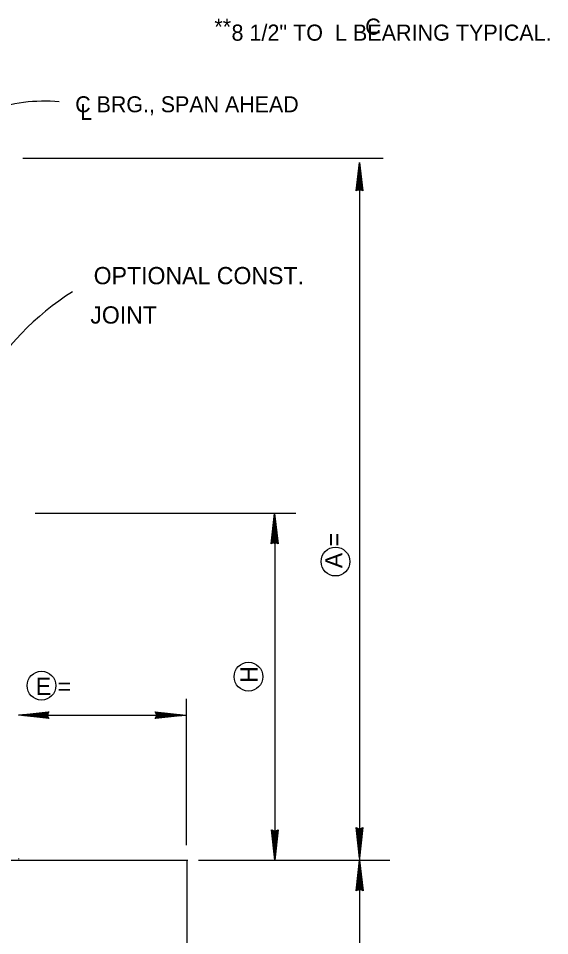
# Model space of a CAD drawing. Extents: x 1.6 to 6.29, y 2.8 to 7.08.
# Drawn here: x 4.232 to 4.616, y 5.231 to 5.896 of the extents above; entities that cross this region are included whole.
import ezdxf

# ---------------------------------------------------------------- set-up
doc = ezdxf.new("R2010")
doc.units = 0
doc.layers.add('Level 1', color=7, linetype='Continuous')
doc.layers.add('Level 5', color=7, linetype='Continuous')

msp = doc.modelspace()

# ---------------------------------------------------------------- linework, layer by layer
at = {"layer": 'Level 1'}
for p, q in [((4.23483, 5.79417), (4.49575, 5.79417)), ((4.47625, 5.77058), (4.47858, 5.79125)), ((4.47858, 5.79125), (4.47858, 5.13608)), ((4.47858, 5.77058), (4.47858, 5.79125)), ((4.47858, 5.79125), (4.48092, 5.77058)), ((4.47658, 5.77108), (4.47825, 5.78642)), ((4.47658, 5.77092), (4.47833, 5.78642)), ((4.47675, 5.77092), (4.47842, 5.78642)), ((4.47683, 5.77092), (4.4785, 5.78633)), ((4.477, 5.77092), (4.47875, 5.78633)), ((4.478, 5.77858), (4.4785, 5.78783)), ((4.47992, 5.77083), (4.47833, 5.78525)), ((4.4785, 5.78783), (4.479, 5.78583)), ((4.48017, 5.77092), (4.47858, 5.78533)), ((4.479, 5.78583), (4.47875, 5.78842)), ((4.47875, 5.78842), (4.47875, 5.772)), ((4.48033, 5.77092), (4.47875, 5.78542)), ((4.48058, 5.77108), (4.479, 5.78542)), ((4.4775, 5.7715), (4.478, 5.77858)), ((4.47833, 5.772), (4.47817, 5.78117)), ((4.47817, 5.78117), (4.4785, 5.78108)), ((4.47833, 5.77933), (4.47817, 5.772)), ((4.4785, 5.78108), (4.47833, 5.77933)), ((4.47908, 5.77175), (4.47842, 5.78233)), ((4.47842, 5.78233), (4.4795, 5.77158)), ((4.47858, 5.77167), (4.47625, 5.77058)), ((4.47842, 5.77208), (4.47692, 5.77108)), ((4.47692, 5.77108), (4.47725, 5.77158)), ((4.47783, 5.7725), (4.47717, 5.77217)), ((4.47717, 5.77217), (4.47867, 5.77183)), ((4.47725, 5.77158), (4.478, 5.77208)), ((4.47775, 5.77608), (4.4775, 5.7715)), ((4.47783, 5.77175), (4.47775, 5.77608)), ((4.478, 5.77792), (4.47783, 5.77175)), ((4.478, 5.77208), (4.47783, 5.7725)), ((4.47817, 5.772), (4.478, 5.77792)), ((4.4795, 5.77158), (4.47842, 5.77208)), ((4.48092, 5.77058), (4.47858, 5.77167)), ((4.47867, 5.77183), (4.4795, 5.7715)), ((4.47875, 5.772), (4.47908, 5.77683)), ((4.47908, 5.77683), (4.47908, 5.77175)), ((4.4795, 5.7715), (4.4805, 5.77108)), ((4.24383, 5.53717), (4.43258, 5.53717)), ((4.41475, 5.515), (4.41717, 5.53708)), ((4.41583, 5.51608), (4.41758, 5.5325)), ((4.41658, 5.52358), (4.41708, 5.53342)), ((4.41708, 5.53342), (4.41758, 5.53133)), ((4.41717, 5.515), (4.41717, 5.53708)), ((4.41717, 5.53708), (4.41967, 5.515)), ((4.41725, 5.53583), (4.41725, 5.28633)), ((4.41758, 5.53133), (4.41733, 5.53408)), ((4.41733, 5.53408), (4.41742, 5.5165)), ((4.41508, 5.51542), (4.41692, 5.53192)), ((4.41517, 5.51542), (4.417, 5.53192)), ((4.41533, 5.51542), (4.41708, 5.53183)), ((4.4155, 5.51542), (4.41733, 5.53183)), ((4.41692, 5.5165), (4.41675, 5.52633)), ((4.41675, 5.52633), (4.41708, 5.52625)), ((4.41858, 5.51533), (4.41692, 5.53067)), ((4.41708, 5.52625), (4.41692, 5.52442)), ((4.41775, 5.51625), (4.417, 5.5275)), ((4.417, 5.5275), (4.41817, 5.51608)), ((4.41883, 5.51542), (4.41717, 5.53075)), ((4.41908, 5.51542), (4.41742, 5.53083)), ((4.41933, 5.5155), (4.41758, 5.53083)), ((4.41608, 5.516), (4.41658, 5.52358)), ((4.41633, 5.52083), (4.41608, 5.516)), ((4.41642, 5.51625), (4.41633, 5.52083)), ((4.41658, 5.52283), (4.41642, 5.51625)), ((4.41675, 5.5165), (4.41658, 5.52283)), ((4.41692, 5.52442), (4.41675, 5.5165)), ((4.41742, 5.5165), (4.41775, 5.52167)), ((4.41775, 5.52167), (4.41775, 5.51625)), ((4.41717, 5.51617), (4.41475, 5.515)), ((4.417, 5.51658), (4.41542, 5.51558)), ((4.41542, 5.51558), (4.41575, 5.51608)), ((4.41642, 5.51708), (4.41567, 5.51675)), ((4.41567, 5.51675), (4.41725, 5.51642)), ((4.41575, 5.51608), (4.41658, 5.51658)), ((4.41658, 5.51658), (4.41642, 5.51708)), ((4.41817, 5.51608), (4.417, 5.51658)), ((4.41967, 5.515), (4.41717, 5.51617)), ((4.41725, 5.51642), (4.41817, 5.516)), ((4.41817, 5.516), (4.41925, 5.5155)), ((4.353, 5.40283), (4.353, 5.29683)), ((4.23158, 5.391), (4.25367, 5.3935)), ((4.25317, 5.39308), (4.23783, 5.39142)), ((4.25317, 5.39292), (4.23783, 5.39125)), ((4.25367, 5.3935), (4.2525, 5.391)), ((4.25267, 5.392), (4.25317, 5.39308)), ((4.33067, 5.39342), (4.35292, 5.391)), ((4.33183, 5.391), (4.33067, 5.39342)), ((4.33108, 5.39308), (4.34767, 5.39125)), ((4.33108, 5.393), (4.34767, 5.39117)), ((4.33108, 5.39292), (4.34767, 5.39108)), ((4.33117, 5.39317), (4.34767, 5.39133)), ((4.25367, 5.391), (4.23158, 5.391)), ((4.25367, 5.38858), (4.23158, 5.391)), ((4.23408, 5.391), (4.35033, 5.391)), ((4.23725, 5.39142), (4.23458, 5.39117)), ((4.23458, 5.39117), (4.25217, 5.39125)), ((4.23525, 5.39083), (4.23725, 5.39142)), ((4.24508, 5.39042), (4.23525, 5.39083)), ((4.25317, 5.38892), (4.23675, 5.39075)), ((4.25317, 5.389), (4.23675, 5.39075)), ((4.25317, 5.38883), (4.23675, 5.39067)), ((4.25325, 5.38933), (4.23683, 5.39108)), ((4.25317, 5.38908), (4.23683, 5.39092)), ((4.25325, 5.39267), (4.23792, 5.391)), ((4.25325, 5.39242), (4.23792, 5.39075)), ((4.24117, 5.39075), (4.2525, 5.392)), ((4.25242, 5.39158), (4.24117, 5.39075)), ((4.24233, 5.39058), (4.24233, 5.39083)), ((4.24233, 5.39083), (4.24425, 5.39075)), ((4.25217, 5.39075), (4.24233, 5.39058)), ((4.24425, 5.39075), (4.25217, 5.39058)), ((4.25258, 5.38983), (4.24508, 5.39042)), ((4.25217, 5.39058), (4.24583, 5.39042)), ((4.24583, 5.39042), (4.25242, 5.39025)), ((4.25217, 5.39125), (4.247, 5.39158)), ((4.247, 5.39158), (4.25242, 5.39158)), ((4.25242, 5.39025), (4.24775, 5.39008)), ((4.24775, 5.39008), (4.25258, 5.38983)), ((4.25208, 5.39042), (4.2515, 5.39017)), ((4.2515, 5.39017), (4.25192, 5.3895)), ((4.25192, 5.3895), (4.25225, 5.39108)), ((4.2525, 5.392), (4.25208, 5.39075)), ((4.25208, 5.39075), (4.253, 5.38925)), ((4.2525, 5.38958), (4.25208, 5.39042)), ((4.25225, 5.39108), (4.25267, 5.392)), ((4.2525, 5.391), (4.25367, 5.38858)), ((4.253, 5.38925), (4.2525, 5.38958)), ((4.33067, 5.391), (4.35292, 5.391)), ((4.35292, 5.391), (4.33067, 5.3885)), ((4.33067, 5.3885), (4.33183, 5.391)), ((4.331, 5.38958), (4.3465, 5.39125)), ((4.33108, 5.39267), (4.34767, 5.39083)), ((4.33108, 5.38933), (4.3465, 5.391)), ((4.33108, 5.38908), (4.34658, 5.39075)), ((4.33117, 5.38883), (4.34658, 5.39058)), ((4.33158, 5.39), (4.33117, 5.38892)), ((4.33225, 5.39117), (4.33125, 5.39275)), ((4.33125, 5.39275), (4.33175, 5.39242)), ((4.332, 5.39092), (4.33158, 5.39)), ((4.3365, 5.39192), (4.33167, 5.39217)), ((4.33167, 5.39217), (4.33933, 5.39158)), ((4.33175, 5.39242), (4.33225, 5.39158)), ((4.34317, 5.39117), (4.33175, 5.39)), ((4.33175, 5.39), (4.33225, 5.39117)), ((4.33192, 5.39175), (4.3365, 5.39192)), ((4.33858, 5.39158), (4.33192, 5.39175)), ((4.33192, 5.39042), (4.34317, 5.39117)), ((4.33733, 5.39042), (4.33192, 5.39042)), ((4.33233, 5.3925), (4.332, 5.39092)), ((4.33217, 5.39142), (4.33858, 5.39158)), ((4.33217, 5.39125), (4.34208, 5.39142)), ((4.34017, 5.39125), (4.33217, 5.39142)), ((4.34992, 5.39083), (4.33217, 5.39075)), ((4.33217, 5.39075), (4.33733, 5.39042)), ((4.33225, 5.39158), (4.33275, 5.39183)), ((4.33275, 5.39183), (4.33233, 5.3925)), ((4.33933, 5.39158), (4.34917, 5.39117)), ((4.342, 5.39117), (4.34017, 5.39125)), ((4.34208, 5.39142), (4.342, 5.39117)), ((4.34917, 5.39117), (4.34717, 5.39058)), ((4.34717, 5.39058), (4.34992, 5.39083)), ((4.41725, 5.286), (4.41483, 5.30808)), ((4.41483, 5.30808), (4.41733, 5.30692)), ((4.41517, 5.30767), (4.41692, 5.29225)), ((4.41625, 5.30717), (4.41525, 5.30767)), ((4.41542, 5.30767), (4.41708, 5.29225)), ((4.41567, 5.30767), (4.41733, 5.29233)), ((4.41592, 5.30767), (4.41767, 5.29242)), ((4.41725, 5.30667), (4.41625, 5.30717)), ((4.41758, 5.29558), (4.41625, 5.307)), ((4.41625, 5.307), (4.41758, 5.3065)), ((4.41675, 5.3015), (4.41675, 5.30692)), ((4.41675, 5.30692), (4.41758, 5.29558)), ((4.41708, 5.30658), (4.41675, 5.3015)), ((4.41717, 5.289), (4.41708, 5.30658)), ((4.41725, 5.30808), (4.41725, 5.286)), ((4.41975, 5.30808), (4.41725, 5.286)), ((4.419, 5.30767), (4.41725, 5.29125)), ((4.41883, 5.30633), (4.41725, 5.30667)), ((4.41733, 5.30692), (4.41975, 5.30808)), ((4.41917, 5.30767), (4.41733, 5.29125)), ((4.41933, 5.30767), (4.41758, 5.29117)), ((4.41758, 5.3065), (4.41908, 5.3075)), ((4.4195, 5.30767), (4.41767, 5.29117)), ((4.41942, 5.30767), (4.41767, 5.29117)), ((4.41767, 5.30658), (4.41767, 5.29675)), ((4.41767, 5.29867), (4.41767, 5.30658)), ((4.41767, 5.30658), (4.418, 5.30025)), ((4.41842, 5.30708), (4.41792, 5.2995)), ((4.41875, 5.307), (4.41792, 5.3065)), ((4.41792, 5.3065), (4.41808, 5.306)), ((4.418, 5.30025), (4.418, 5.30692)), ((4.418, 5.30692), (4.41817, 5.30225)), ((4.41817, 5.30225), (4.41842, 5.30708)), ((4.41908, 5.3075), (4.41875, 5.307)), ((4.47858, 5.2875), (4.47617, 5.30958)), ((4.47617, 5.30958), (4.47867, 5.30842)), ((4.4765, 5.30917), (4.47825, 5.29375)), ((4.47758, 5.30867), (4.47658, 5.30917)), ((4.47675, 5.30917), (4.47842, 5.29375)), ((4.477, 5.30917), (4.47867, 5.29383)), ((4.47725, 5.30917), (4.479, 5.29392)), ((4.47858, 5.30817), (4.47758, 5.30867)), ((4.47892, 5.29708), (4.47758, 5.3085)), ((4.47758, 5.3085), (4.47892, 5.308)), ((4.47808, 5.303), (4.47808, 5.30842)), ((4.47808, 5.30842), (4.47892, 5.29708)), ((4.47842, 5.30808), (4.47808, 5.303)), ((4.4785, 5.2905), (4.47842, 5.30808)), ((4.47858, 5.30958), (4.47858, 5.2875)), ((4.48108, 5.30958), (4.47858, 5.2875)), ((4.48033, 5.30917), (4.47858, 5.29275)), ((4.48017, 5.30783), (4.47858, 5.30817)), ((4.47867, 5.30842), (4.48108, 5.30958)), ((4.4805, 5.30917), (4.47867, 5.29275)), ((4.48067, 5.30917), (4.47892, 5.29267)), ((4.47892, 5.308), (4.48042, 5.309)), ((4.48083, 5.30917), (4.479, 5.29267)), ((4.48075, 5.30917), (4.479, 5.29267)), ((4.479, 5.30808), (4.479, 5.29825)), ((4.479, 5.30017), (4.479, 5.30808)), ((4.479, 5.30808), (4.47933, 5.30175)), ((4.47975, 5.30858), (4.47925, 5.301)), ((4.48008, 5.3085), (4.47925, 5.308)), ((4.47925, 5.308), (4.47942, 5.3075)), ((4.47933, 5.30175), (4.47933, 5.30842)), ((4.47933, 5.30842), (4.4795, 5.30375)), ((4.47942, 5.3075), (4.48017, 5.30783)), ((4.4795, 5.30375), (4.47975, 5.30858)), ((4.48042, 5.309), (4.48008, 5.3085)), ((4.41808, 5.306), (4.41883, 5.30633)), ((4.47925, 5.301), (4.47875, 5.29117)), ((4.47875, 5.29833), (4.479, 5.30017)), ((4.41792, 5.2995), (4.41742, 5.28967)), ((4.41742, 5.29683), (4.41767, 5.29867)), ((4.41767, 5.29675), (4.41742, 5.29683)), ((4.47875, 5.29117), (4.47825, 5.29325)), ((4.47825, 5.29325), (4.4785, 5.2905)), ((4.479, 5.29825), (4.47875, 5.29833)), ((4.23167, 5.28733), (4.23167, 5.28683)), ((4.41742, 5.28967), (4.41692, 5.29175)), ((4.41692, 5.29175), (4.41717, 5.289)), ((4.16858, 5.286), (4.35417, 5.286)), ((4.3535, 5.28533), (4.3535, 5.13483)), ((4.36208, 5.286), (4.50067, 5.286)), ((4.47625, 5.26392), (4.47867, 5.286)), ((4.47658, 5.26442), (4.47833, 5.28083)), ((4.47658, 5.26433), (4.47842, 5.28083)), ((4.47667, 5.26433), (4.4785, 5.28083)), ((4.47683, 5.26433), (4.47858, 5.28075)), ((4.477, 5.26433), (4.47883, 5.28075)), ((4.47808, 5.2725), (4.47858, 5.28233)), ((4.47858, 5.28233), (4.47908, 5.28025)), ((4.47867, 5.26392), (4.47867, 5.286)), ((4.47867, 5.286), (4.48117, 5.26392)), ((4.47908, 5.28025), (4.47883, 5.283)), ((4.47883, 5.283), (4.47892, 5.26542)), ((4.47842, 5.26542), (4.47825, 5.27525)), ((4.47825, 5.27525), (4.47858, 5.27517)), ((4.47842, 5.27333), (4.47825, 5.26542)), ((4.48008, 5.26425), (4.47842, 5.27958)), ((4.47858, 5.27517), (4.47842, 5.27333)), ((4.47925, 5.26517), (4.4785, 5.27642)), ((4.4785, 5.27642), (4.47967, 5.265)), ((4.48033, 5.26433), (4.47867, 5.27967)), ((4.48058, 5.26433), (4.47892, 5.27975)), ((4.48083, 5.26442), (4.47908, 5.27975)), ((4.47758, 5.26492), (4.47808, 5.2725)), ((4.47783, 5.26975), (4.47758, 5.26492)), ((4.47792, 5.26517), (4.47783, 5.26975)), ((4.47808, 5.27175), (4.47792, 5.26517)), ((4.47825, 5.26542), (4.47808, 5.27175)), ((4.47892, 5.26542), (4.47925, 5.27058)), ((4.47925, 5.27058), (4.47925, 5.26517)), ((4.47867, 5.26508), (4.47625, 5.26392)), ((4.4785, 5.2655), (4.47692, 5.2645)), ((4.47692, 5.2645), (4.47725, 5.265)), ((4.47792, 5.266), (4.47717, 5.26567)), ((4.47717, 5.26567), (4.47875, 5.26533)), ((4.47725, 5.265), (4.47808, 5.2655)), ((4.47808, 5.2655), (4.47792, 5.266)), ((4.47967, 5.265), (4.4785, 5.2655)), ((4.48117, 5.26392), (4.47867, 5.26508)), ((4.47875, 5.26533), (4.47967, 5.26492)), ((4.47967, 5.26492), (4.48075, 5.26442))]:
    msp.add_line(p, q, dxfattribs=at)
for centre in [(4.46119, 5.50221), (4.39819, 5.41887), (4.24827, 5.41237)]:
    msp.add_circle(centre, 0.01042, dxfattribs=at)
for centre, radius, start, end in [((4.25019, 5.71746), 0.11807, 84.66253, 109.74805), ((4.37292, 5.5346), 0.19231, 122.06338, 178.61588)]:
    msp.add_arc(centre, radius, start, end, dxfattribs=at)

# ---------------------------------------------------------------- texts
for s, height, p in [('**', 0.011666, (4.3735, 5.88358)), ('  8 1/2" TO  L BEARING TYPICAL.', 0.0116665, (4.37725, 5.87933)), ('C', 0.01167, (4.48275, 5.88367)), ('C BRG., SPAN AHEAD', 0.0115835, (4.27275, 5.8275)), ('L', 0.01158, (4.27642, 5.822)), ('OPTIONAL CONST.', 0.0125, (4.28608, 5.703)), ('JOINT   ', 0.0125, (4.28367, 5.6745))]:
    msp.add_text(s, height=height, dxfattribs=at).set_placement(p)
msp.add_text('H', height=0.0125, rotation=90, dxfattribs=at).set_placement((4.40483, 5.41442))
at = {"layer": 'Level 5'}
msp.add_text('A =      ', height=0.0125, rotation=90, dxfattribs=at).set_placement((4.46625, 5.49742))
msp.add_text('E =      ', height=0.0125, dxfattribs=at).set_placement((4.24417, 5.40567))

doc.saveas('drawing.dxf')
